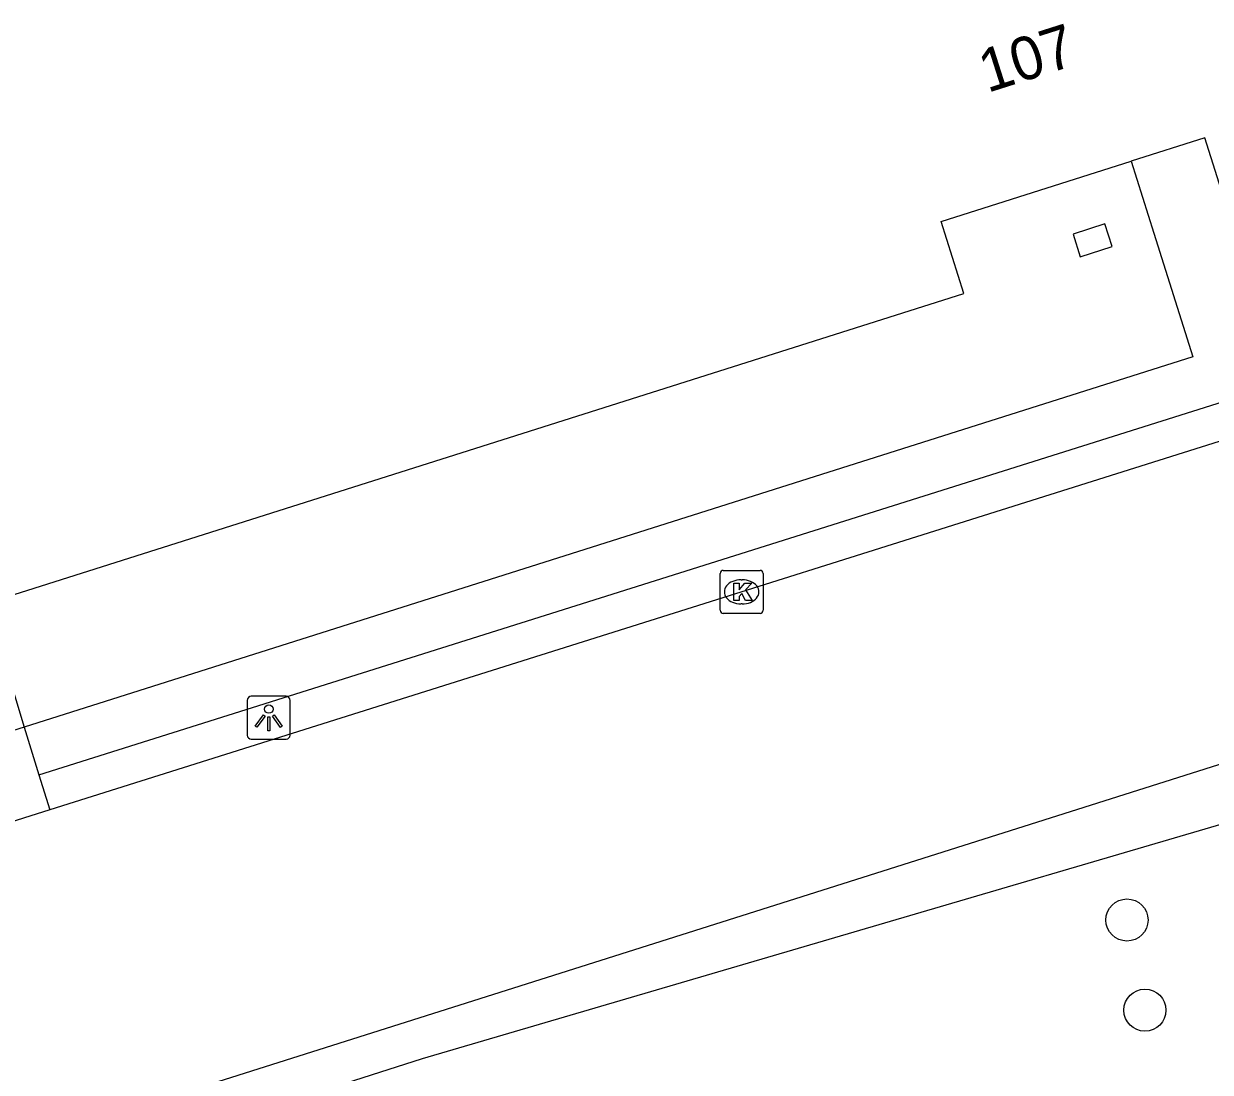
# Model space of a CAD drawing. Extents: x 161389 to 162585, y 388479 to 389761.
# Drawn here: x 162279.11 to 162306.65, y 388570.17 to 388594.52 of the extents above; entities that cross this region are included whole.
import ezdxf

# ---------------------------------------------------------------- set-up
doc = ezdxf.new("R2010")
doc.units = 0
for name, color, linetype in [('IMGEO_Berm_groen', 7, 'Continuous'), ('IMGEO_Boom', 7, 'Continuous'), ('IMGEO_Groenvoorziening', 7, 'Continuous'), ('IMGEO_Kolk', 7, 'Continuous'), ('IMGEO_Lichtpunt', 7, 'Continuous'), ('IMGEO_Pand', 7, 'Continuous'), ('IMGEO_Pand_nummerreeks', 7, 'Continuous'), ('IMGEO_Rijbaan_lokaal_gesloten', 7, 'Continuous'), ('IMGEO_Voetpad_open', 7, 'Continuous')]:
    doc.layers.add(name, color=color, linetype=linetype)

msp = doc.modelspace()

# ---------------------------------------------------------------- linework, layer by layer
at = {"layer": 'IMGEO_Berm_groen'}
msp.add_lwpolyline([(162138.38, 388518.892), (162215.574, 388546.64), (162252.986, 388559.158), (162288.362, 388570.488), (162317.268, 388578.974), (162336.532, 388584.978)], dxfattribs=at)
at = {"layer": 'IMGEO_Boom'}
for centre in [(162304.72, 388573.706), (162305.137, 388571.613)]:
    msp.add_circle(centre, 0.489, dxfattribs=at)
at = {"layer": 'IMGEO_Groenvoorziening'}
msp.add_lwpolyline([(162278.245, 388581.061), (162279.121, 388578.182)], dxfattribs=at)
at = {"layer": 'IMGEO_Kolk'}
for p, q in [((162295.274, 388580.898), (162295.274, 388581.75)), ((162295.349, 388581.824), (162296.201, 388581.824)), ((162295.762, 388581.604), (162295.787, 388581.604)), ((162296.275, 388581.75), (162296.275, 388580.898)), ((162295.785, 388581.044), (162295.76, 388581.044)), ((162296.201, 388580.824), (162295.349, 388580.824))]:
    msp.add_line(p, q, dxfattribs=at)
for points in [[(162295.274, 388580.898), (162295.274, 388581.75)], [(162295.349, 388581.824), (162296.201, 388581.824)], [(162296.275, 388581.75), (162296.275, 388580.898)], [(162295.595, 388581.524), (162295.718, 388581.524), (162295.718, 388581.373), (162295.848, 388581.524), (162296.012, 388581.524), (162295.866, 388581.373), (162296.019, 388581.124), (162295.867, 388581.124), (162295.782, 388581.288), (162295.718, 388581.221), (162295.718, 388581.124), (162295.595, 388581.124), (162295.595, 388581.524)], [(162296.201, 388580.824), (162295.349, 388580.824)]]:
    msp.add_lwpolyline(points, dxfattribs=at)
for centre, start, end in [((162295.351, 388581.748), 91.552, 178.448), ((162295.351, 388581.748), 91.552, 178.448), ((162296.199, 388581.748), 1.552, 88.448), ((162296.199, 388581.748), 1.552, 88.448), ((162295.351, 388580.9), 181.552, 268.448), ((162295.351, 388580.9), 181.552, 268.448), ((162296.199, 388580.9), 271.552, 358.448), ((162296.199, 388580.9), 271.552, 358.448)]:
    msp.add_arc(centre, 0.0765, start, end, dxfattribs=at)
for centre, major_axis, ratio, start_param, end_param in [((162295.761, 388581.324), (-0.387, 0.002), 0.722429, 4.712389, 7.853982), ((162295.786, 388581.324), (-0.39, 0.002), 0.717154, 1.570796, 4.712389)]:
    msp.add_ellipse(centre, major_axis=major_axis, ratio=ratio, start_param=start_param, end_param=end_param, dxfattribs=at)
at = {"layer": 'IMGEO_Lichtpunt'}
for p, q in [((162285.199, 388578.901), (162284.391, 388578.901)), ((162285.199, 388578.901), (162284.391, 388578.901)), ((162284.297, 388578.806), (162284.297, 388577.999)), ((162284.297, 388578.806), (162284.297, 388577.999)), ((162285.293, 388577.999), (162285.293, 388578.806)), ((162285.293, 388577.999), (162285.293, 388578.806)), ((162284.391, 388577.905), (162285.199, 388577.905)), ((162284.391, 388577.905), (162285.199, 388577.905))]:
    msp.add_line(p, q, dxfattribs=at)
for points in [[(162284.671, 388578.47), (162284.71, 388578.442), (162284.522, 388578.18), (162284.484, 388578.207), (162284.671, 388578.47)], [(162284.773, 388578.422), (162284.82, 388578.422), (162284.82, 388578.1), (162284.773, 388578.1), (162284.773, 388578.422)], [(162284.883, 388578.442), (162284.921, 388578.469), (162285.108, 388578.207), (162285.069, 388578.179), (162284.883, 388578.442)]]:
    msp.add_lwpolyline(points, dxfattribs=at)
msp.add_circle((162284.796, 388578.604), 0.0994, dxfattribs=at)
for centre, start, end in [((162284.391, 388578.806), 90, 180), ((162284.391, 388578.806), 90, 180), ((162285.199, 388578.806), 0, 90), ((162285.199, 388578.806), 0, 90), ((162284.391, 388577.999), 180, 270), ((162284.391, 388577.999), 180, 270), ((162285.199, 388577.999), 270, 0), ((162285.199, 388577.999), 270, 360)]:
    msp.add_arc(centre, 0.0946, start, end, dxfattribs=at)
at = {"layer": 'IMGEO_Pand'}
for points in [[(162307.058, 388590.201), (162306.532, 388591.87), (162304.816, 388591.324)], [(162278.245, 388581.061), (162300.935, 388588.252), (162300.406, 388589.921), (162304.816, 388591.324)], [(162304.21, 388589.867), (162303.47, 388589.631), (162303.637, 388589.107), (162304.377, 388589.343), (162304.21, 388589.867)]]:
    msp.add_lwpolyline(points, dxfattribs=at)
at = {"layer": 'IMGEO_Rijbaan_lokaal_gesloten'}
for points in [[(162314.748, 388587.303), (162279.715, 388576.261)], [(162316.848, 388580.491), (162315.105, 388579.927), (162225.932, 388551.675), (162217.932, 388548.854), (162137.852, 388520.378)], [(162279.715, 388576.261), (162276.796, 388575.341), (162269.879, 388573.06), (162262.278, 388570.688)]]:
    msp.add_lwpolyline(points, dxfattribs=at)
at = {"layer": 'IMGEO_Voetpad_open'}
for points in [[(162304.816, 388591.324), (162305.344, 388589.653), (162306.251, 388586.783), (162279.121, 388578.182)], [(162279.459, 388577.073), (162316.168, 388588.644)], [(162279.121, 388578.182), (162268.122, 388574.718)], [(162279.121, 388578.182), (162279.459, 388577.073)], [(162279.459, 388577.073), (162279.715, 388576.261)]]:
    msp.add_lwpolyline(points, dxfattribs=at)

# ---------------------------------------------------------------- texts
at = {"layer": 'IMGEO_Pand_nummerreeks'}
msp.add_text('107', height=1, rotation=17.6528, dxfattribs=at).set_placement((162301.481, 388592.907))

doc.saveas('drawing.dxf')
